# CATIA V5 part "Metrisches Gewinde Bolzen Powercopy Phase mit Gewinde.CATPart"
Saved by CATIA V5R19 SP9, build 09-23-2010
Part number: Metrisches Gewinde
Bounding box of the stored display mesh (mm): x -4 to 4, y -4 to 4, z -8 to 6.5
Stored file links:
  E:\Markus\CATIA\_Standards\Metrisches Gewinde Bolzen Powercopy Phase mit Gewinde.CATPart
  E:\Markus\CATIA\_Standards\Metrisches Gewinde.txt
  Unbenannt-M8x20-Gewindestange.CATPart
  d:\Program Files\Dassault Systemes\B19\win_b64\reffiles\standard\MetricThickPitch.txt
  E:\Markus\CATIA\_Standards\Metrisches Gewinde 2.CATPart
  E:\Markus\CATIA\_Standards\Metrisches Gewinde Mutter Powercopy.CATPart
  d:\Program Files\Dassault Systemes\B19\win_b64\reffiles\standard\MetricThinPitch.txt
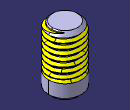
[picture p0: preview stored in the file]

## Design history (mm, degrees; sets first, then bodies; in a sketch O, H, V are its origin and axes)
Parameters
  DurchmesserBolzen = 8 mm
Set1 "Gewinde Bolzen mit Fase"
  Extract1 "AbleitenStirnfläche": ExtractElem end face of Pad1
  Boundary1 "BegrenzungStirnfläche": Boundary Extract1
  Point1 "MitteGewinde": type Center, Curve Boundary1
  Line1 "GewindeAchse": type PtDir, RefPoint Point1, Direction Extract1, Start 0, End 10 {= Thread1.Depth +`VerlängerunGewinde`}
  Point2 "EndeGewinde": type OnCurve, Support Line1, Ratio 1
  Line2 "Y-Richtung": type PtDir, RefPoint Point1, Direction (0, 1, 0), Start 0, End 4
  Line3 "PlaneRichtung": stored without definition
  Plane1 "SkizzenEbene": type 2Lines, Element1 Line1, Element2 Line3
  Line4 "LinieStartHelix": type Angle, RefPoint Point1, Curve Line1, Support Plane1, Start 0, End 4 {= Thread1.Diameter /2}, Angle 90
  Point3 "StartpunktHelix": type OnCurve, Support Line4, Ratio 1
  Helix1 "HelixGewinde": Direction Line1, RefPoint Point3, Pitch 1.25 {= Thread1.Pitch}, Height 12.5 {= Thread1.Depth  +Thread1.Pitch * 2 + `VerlängerunGewinde`}, TaperAngle 0
  Sketch1 "GewindeSkizze" on Plane1, origin (0, 0, 6.5), H (0, 1, 0), V (0, 0, -1)
    line L1 (5, 0.625) -> (4.0451, 0.625)
    arc A1 centre (3.4136, 0) radius 0.1804 from (3.3234, 0.1562) to (3.3234, -0.1562) ccw
    point P3 (3.4136, 0)
    line L2 (3.3234, -0.1562) -> (4, -0.5469)
    line L3 (5, -0.625) -> (5, 0.625)
    line L4 (4, 0.5469) -> (3.3234, 0.1562)
    line L5 (4.0451, -0.625) -> (5, -0.625)
    arc A2 centre (3.9549, 0.625) radius 0.0902 from (4, 0.5469) to (4.0451, 0.625) ccw
    point P6 (4, 0.5469)
    point P7 (3.9549, 0.625)
    arc A3 centre (3.9549, -0.625) radius 0.0902 from (4.0451, -0.625) to (4, -0.5469) ccw
    point P9 (3.9549, -0.625)
    construction line L6 (3.9549, 0.625) -> (3.9549, -0.625)
    angle L2 L4 = 60
    length L3 = 1.25 {= Thread1.Pitch}
    radius A1 = 0.1804 {= 0.1443*Thread1.Pitch}
    distance A1 V = 3.2332 {= (Thread1.Diameter  -1.2269*Thread1.Pitch )/2+`Set1.Gewinde Offset`}
    radius A2 = 0.0902 (reference)
    radius A3 = 0.0902 (reference)
    distance V P6 = 4 {= Thread1.Diameter /2+`Set1.Gewinde Offset`}
    length L1 = 0.9549
    tangency: A1 L4, L2 A1, A2 L4, A3 L2
    vertical: L3 V, L6 V
    coincidence: P3 H, P7 L1, P9 L5
    symmetry: L4 L2 H, L1 L5 H
    horizontal: L5 H, L1 H
  Extract2: ExtractElem Sketch1.A2
  Extract3: ExtractElem Sketch1.L4
  Extract4: ExtractElem Sketch1.A1
  Join1: Elements (Extract4; Extract3; Extract2)
  Extract5: ExtractElem Sketch1.L2
  Extract6: ExtractElem Sketch1.A3
  Join2: Elements (Extract6; Extract5)
  Sweep1: type Unspec, Profile Join1, Guide Helix1, AngleRef 0, PullingDir Line1
  Sweep2: type Unspec, Profile Join2, Guide Helix1, AngleRef 0, PullingDir Line1
  Trim1 "GewindeLang": Trimmed (Sweep1; Sweep2)
  Sketch2 "SkizzeGewindeEnde" on Plane1, origin (0, 0, -3.5), H (0, 1, 0), V (0, 0, -1)
    line L1 (3.2332, 0) -> (4.0902, 0.4948)
    point P1 (3.2332, 0)
    point P2 (4.0902, 0.4948)
    distance P1 V = 3.2332 {= (Thread1.Diameter   -1.2269 * Thread1.Pitch  )/2+`Set1.Gewinde Offset`}
    distance P2 V = 4.0902 {= max(Thread1.Diameter /2 , Thread1.Diameter /2 +`Set1.Gewinde Offset` +0.1443*Thread1.Pitch /2)}
    angle L1 H = 30 {= 30deg * List(PhaseAmGweindeauslauf )->IndexOf(true,0)}
    coincidence: P1 H
  Revol1: Element1 Sketch2, Line Line1, Angle1 360
  Trim2 "GewindeGekürzt": Trimmed (Revol1; Trim1)
  DatumSurface1
Body1 "Bolzen" (main body)
  Sketch3 on xy-plane, origin (0, 0, 0), H (1, 0, 0), V (0, 1, 0)
    circle A1 centre (0, 0) radius 4
    radius A1 = 4 {= DurchmesserBolzen /2}
  Pad1: profile Sketch3, direction (0, 0, 1), length 6.5, opposite side length 8
  Chamfer1 "Fase": length 1, angle 45, on end face of Pad1; start face of Pad1
  Thread1 "Gewinde": "M8", diameter 8, depth 10, pitch 1.25, on face of Pad1 from Sketch3.A1, from end face of Pad1
  Split1 "TrennenGewinde": SplitPlane DatumSurface1
Relations
  Line3 = line(Point1  ,direction(List(int(mod(angle(Line1  ,Line2 )/1deg ,180)) )->IndexOf(0,0)*10mm ,mod(angle(Line1  ,Line2  )/1deg ,180)*10mm ,0mm) ,0mm,10mm,true)
  DatumSurface1 = List(Trim2 ,symmetry(Trim2 ,Plane1 ))->GetItem( 1 + List(Thread1.RotationSide )->IndexOf(true,0) )
  Thread1.ThreadDescription = "M" + DurchmesserBolzen /1mm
